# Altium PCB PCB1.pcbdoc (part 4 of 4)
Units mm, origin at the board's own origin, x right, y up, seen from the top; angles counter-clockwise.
Board outline 96.27 x 122.17 mm, 4 copper layers (Top Layer, Inner1, Inner2, Bottom Layer); 129 components, 127 nets, 708 pads, 342 vias.
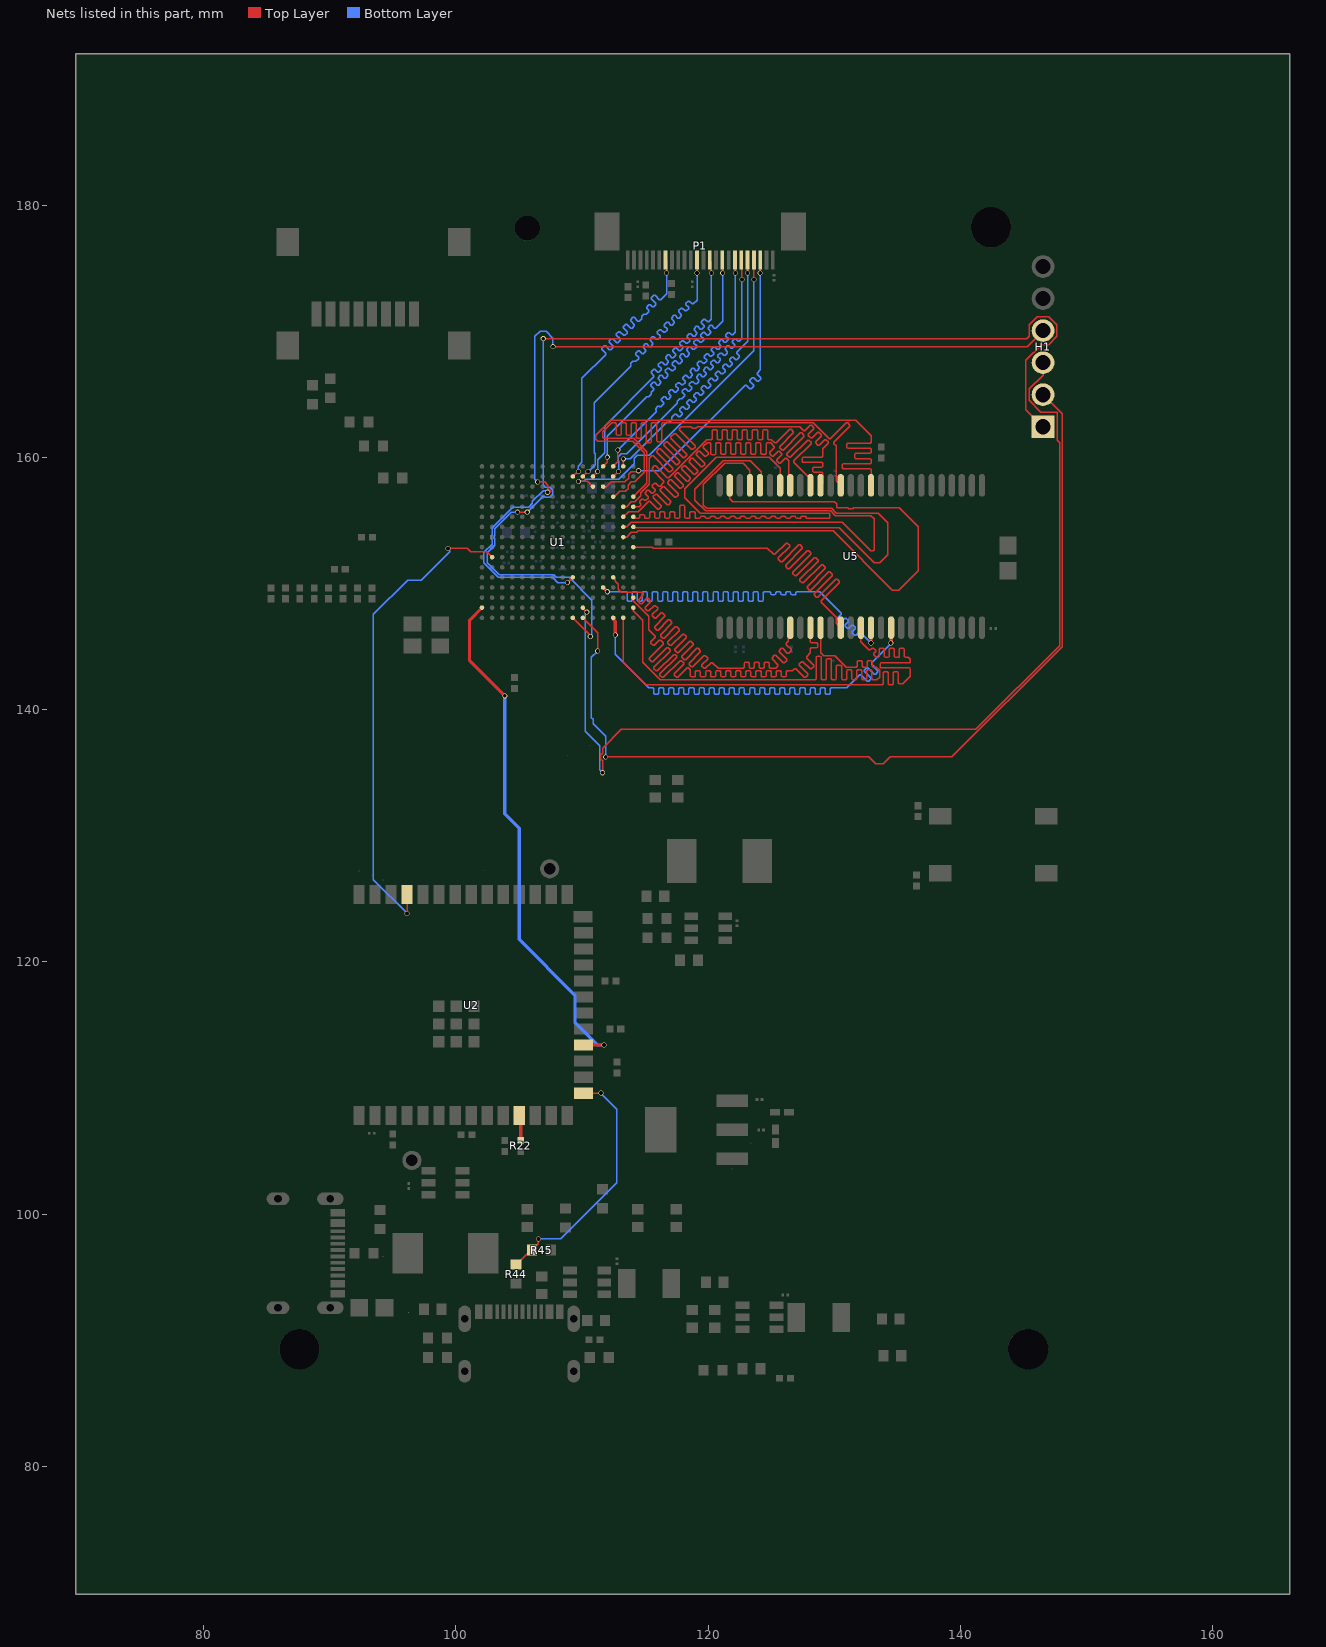
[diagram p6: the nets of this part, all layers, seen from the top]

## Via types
v1: diameter 0.4, hole 0.3, Top Layer to Bottom Layer, 308 vias
v2: diameter 1, hole 0.5, Top Layer to Bottom Layer, 33 vias
v3: diameter 0.5, hole 0.3, Top Layer to Bottom Layer, 1 vias

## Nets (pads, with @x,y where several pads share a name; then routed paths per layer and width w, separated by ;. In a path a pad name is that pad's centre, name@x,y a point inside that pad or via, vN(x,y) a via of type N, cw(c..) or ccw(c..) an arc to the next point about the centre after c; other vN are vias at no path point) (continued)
SD_DQ4: U1.M14 U5.8 | length 46.8
  Top Layer w0.1: U1.M14@112.477,150.489 112.659,150.307 112.659,150.175 112.895,149.939 112.895,149.531 113.119,149.307 114.766,149.307 114.87,149.203 114.87,149.103 114.449,148.682 114.449,148.582 114.632,148.399 114.732,148.399 115.153,148.82 115.253,148.82 115.436,148.637 115.436,148.537 115.015,148.116 115.015,148.016 115.197,147.833 115.297,147.833 115.719,148.254 115.819,148.254 116.002,148.072 116.002,147.972 115.58,147.55 115.58,147.45 115.763,147.267 115.863,147.267 116.284,147.689 116.384,147.689 116.578,147.496 116.578,147.396 115.768,146.587 115.768,146.487 115.951,146.304 116.051,146.304 116.86,147.113 116.96,147.113 117.133,146.94 117.133,146.84 116.232,145.939 116.232,145.839 116.415,145.656 116.515,145.656 117.416,146.557 117.516,146.557 117.699,146.375 117.699,146.275 116.798,145.374 116.798,145.274 116.981,145.091 117.081,145.091 117.982,145.992 118.082,145.992 118.264,145.809 118.264,145.709 117.363,144.808 117.363,144.708 117.546,144.525 117.646,144.525 118.547,145.426 118.647,145.426 118.83,145.243 118.83,145.143 117.929,144.242 117.929,144.142 118.112,143.959 118.212,143.959 119.113,144.86 119.213,144.86 119.396,144.678 119.396,144.578 118.495,143.677 118.495,143.577 118.678,143.394 118.778,143.394 119.679,144.295 119.779,144.295 119.961,144.112 119.961,144.012 119.507,143.558 119.507,143.458 119.69,143.275 119.79,143.275 120.244,143.729 120.344,143.729 120.798,143.275 122.781,143.275 122.852,143.346 122.852,143.693 122.923,143.764 123.181,143.764 123.252,143.693 123.252,143.346 123.323,143.275 123.581,143.275 123.652,143.346 123.652,143.693 123.723,143.764 123.981,143.764 124.052,143.693 124.052,143.346 124.123,143.275 124.381,143.275 124.452,143.346 124.452,143.693 124.523,143.764 124.781,143.764 124.852,143.693 124.852,143.346 124.923,143.275 125.35,143.275 125.533,143.458 125.533,143.558 125.07,144.02 125.07,144.12 125.253,144.303 125.353,144.303 125.954,143.703 126.054,143.703 126.236,143.886 126.236,143.986 125.636,144.586 125.636,144.686 125.819,144.869 125.919,144.869 126.294,144.493 126.394,144.493 126.577,144.676 126.577,144.776 126.202,145.152 126.202,145.252 126.365,145.415 126.365,146.351 U5.8@126.518,146.504
SD_DQ5: U1.P16 U5.10 | length 46.8
  Top Layer w0.1: U1.P16@114.077,148.889 114.077,148.629 115.316,147.39 115.316,146.331 115.815,145.832 115.815,145.732 115.464,145.381 115.464,145.281 115.647,145.098 115.747,145.098 116.148,145.499 116.248,145.499 116.457,145.29 116.457,145.19 115.351,144.083 115.351,143.983 115.534,143.8 115.634,143.8 116.74,144.907 116.84,144.907 116.997,144.75 116.997,144.65 115.704,143.358 115.704,143.258 115.887,143.075 115.987,143.075 117.279,144.368 117.406,144.368 117.499,144.275 117.499,144.175 116.174,142.85 116.174,142.75 116.357,142.567 116.457,142.567 117.782,143.892 117.882,143.892 118.058,143.716 118.058,143.589 117.319,142.85 117.319,142.75 117.502,142.567 117.602,142.567 118.341,143.306 118.441,143.306 118.598,143.149 118.598,142.667 118.669,142.596 118.927,142.596 118.998,142.667 118.998,143.004 119.069,143.075 119.327,143.075 119.398,143.004 119.398,142.667 119.469,142.596 119.727,142.596 119.798,142.667 119.798,143.004 119.869,143.075 120.127,143.075 120.198,143.004 120.198,142.667 120.269,142.596 120.527,142.596 120.598,142.667 120.598,143.004 120.669,143.075 120.927,143.075 120.998,143.004 120.998,142.667 121.069,142.596 121.327,142.596 121.398,142.667 121.398,143.004 121.469,143.075 121.727,143.075 121.798,143.004 121.798,142.667 121.869,142.596 122.127,142.596 122.198,142.667 122.198,143.004 122.269,143.075 122.527,143.075 122.598,143.004 122.598,142.667 122.669,142.596 122.927,142.596 122.998,142.667 122.998,143.004 123.069,143.075 123.327,143.075 123.398,143.004 123.398,142.667 123.469,142.596 123.727,142.596 123.798,142.667 123.798,143.004 123.869,143.075 124.127,143.075 124.198,143.004 124.198,142.667 124.269,142.596 124.527,142.596 124.598,142.667 124.598,143.004 124.669,143.075 124.927,143.075 124.998,143.004 124.998,142.667 125.069,142.596 125.327,142.596 125.398,142.667 125.398,143.004 125.469,143.075 125.727,143.075 125.798,143.004 125.798,142.667 125.869,142.596 126.127,142.596 126.198,142.667 126.198,143.004 126.269,143.075 126.692,143.075 126.859,143.242 126.959,143.242 127.634,142.567 127.734,142.567 127.917,142.75 127.917,142.85 127.242,143.525 127.242,143.625 127.425,143.808 127.525,143.808 128.099,143.234 128.199,143.234 128.381,143.417 128.381,143.517 127.808,144.091 127.808,144.191 128.118,144.501 128.118,144.823 128.189,144.893 128.618,144.893 128.689,144.964 128.689,145.223 128.618,145.293 128.189,145.293 128.118,145.364 U5.10@128.118,146.504
SD_DQ6: U1.R16 U5.11 | length 46.8
  Top Layer w0.1: U1.R16@114.077,148.089 114.077,147.858 114.829,147.106 114.829,143.743 116.205,142.367 128.511,142.367 128.581,142.438 128.581,144.179 128.652,144.249 128.911,144.249 128.981,144.179 128.981,142.438 129.052,142.367 129.311,142.367 129.381,142.438 129.381,143.984 129.452,144.055 129.711,144.055 129.781,143.984 129.781,142.438 129.852,142.367 130.111,142.367 130.181,142.438 130.181,143.456 130.252,143.526 130.511,143.526 130.581,143.456 130.581,142.438 130.652,142.367 130.911,142.367 130.981,142.438 130.981,143.083 131.052,143.154 131.311,143.154 131.381,143.083 131.381,142.438 131.452,142.367 131.711,142.367 131.781,142.438 131.781,143.083 131.852,143.154 132.111,143.154 132.181,143.083 132.181,142.438 132.252,142.367 132.511,142.367 132.581,142.438 132.581,143.083 132.652,143.154 132.911,143.154 132.981,143.083 132.981,142.438 133.052,142.367 133.389,142.367 133.604,142.582 133.604,143.129 133.35,143.383 133.107,143.383 133.037,143.454 133.037,143.82 132.966,143.891 132.707,143.891 132.637,143.82 132.637,143.454 132.566,143.383 132.307,143.383 132.237,143.454 132.237,143.82 132.166,143.891 131.907,143.891 131.837,143.82 131.837,143.454 131.766,143.383 130.937,143.383 130.036,144.284 129.159,144.284 128.918,144.525 U5.11@128.918,146.504
SD_DQ7: U1.J16 U5.13 | length 46.8
  Top Layer w0.1: U1.J16@114.077,152.889 115.588,152.889 115.66,152.817 124.694,152.817 125.201,152.31 125.301,152.31 126.193,153.202 126.293,153.202 126.476,153.019 126.476,152.919 125.584,152.027 125.584,151.927 125.767,151.745 125.867,151.745 127.194,153.072 127.294,153.072 127.477,152.889 127.477,152.789 126.149,151.462 126.149,151.362 126.332,151.179 126.432,151.179 127.869,152.616 127.969,152.616 128.152,152.433 128.152,152.333 126.715,150.896 126.715,150.796 126.898,150.613 126.998,150.613 128.435,152.05 128.535,152.05 128.718,151.867 128.718,151.767 127.281,150.33 127.281,150.23 127.464,150.048 127.564,150.048 129.001,151.485 129.101,151.485 129.284,151.302 129.284,151.202 127.847,149.765 127.847,149.665 128.029,149.482 128.129,149.482 129.566,150.919 129.666,150.919 129.849,150.736 129.849,150.636 128.412,149.199 128.412,149.099 128.595,148.916 128.695,148.916 130.132,150.353 130.232,150.353 130.415,150.17 130.415,150.07 128.978,148.633 128.978,148.533 130.17,147.341 130.17,146.852 U5.13@130.518,146.504
SD_DQ8: U1.D16 U5.42 | length 46.7
  Top Layer w0.1: U1.D16@114.077,156.889 115.156,157.968 115.156,160.463 114.103,161.516 111.733,161.516 111.633,161.616 111.633,162.023 112.351,162.741 112.644,162.741 112.714,162.67 112.714,161.816 112.785,161.745 113.044,161.745 113.114,161.816 113.114,162.67 113.185,162.741 113.444,162.741 113.514,162.67 113.514,161.816 113.585,161.745 113.844,161.745 113.914,161.816 113.914,162.67 113.985,162.741 114.244,162.741 114.314,162.67 114.314,161.587 114.385,161.517 114.644,161.517 114.714,161.587 114.714,162.67 114.785,162.741 115.044,162.741 115.114,162.67 115.114,161.234 115.185,161.163 115.444,161.163 115.514,161.234 115.514,162.67 115.585,162.741 115.844,162.741 115.914,162.67 115.914,161.304 115.985,161.234 116.244,161.234 116.314,161.304 116.314,162.67 116.385,162.741 128.343,162.741 129.602,161.482 129.702,161.482 130.96,162.741 131.06,162.741 131.243,162.558 131.243,162.458 129.985,161.199 129.985,161.099 130.17,160.914 130.17,158.136 U5.42@130.518,157.788
SD_DQ9: U1.E15 U5.44 | length 46.9
  Top Layer w0.1: U1.E15@113.277,156.089 113.537,156.089 113.919,156.471 114.199,156.471 114.681,156.953 114.681,157.21 115.356,157.885 115.356,159.933 115.538,160.115 115.638,160.115 116.9,158.853 117,158.853 117.183,159.036 117.183,159.136 115.921,160.398 115.921,160.498 116.104,160.681 116.204,160.681 117.466,159.419 117.566,159.419 117.749,159.602 117.749,159.702 116.487,160.964 116.487,161.064 116.67,161.247 116.77,161.247 118.032,159.985 118.132,159.985 118.314,160.168 118.314,160.268 117.053,161.53 117.053,161.63 117.321,161.898 117.421,161.898 118.682,160.636 118.782,160.636 118.965,160.819 118.965,160.919 117.703,162.18 117.703,162.28 117.856,162.433 118.643,162.433 118.77,162.306 119.043,162.306 119.17,162.433 127.254,162.433 127.578,162.109 127.678,162.109 128.111,162.541 128.211,162.541 128.394,162.358 128.394,162.258 127.961,161.826 127.961,161.726 128.144,161.543 128.244,161.543 128.68,161.979 128.78,161.979 128.963,161.796 128.963,161.696 128.527,161.26 128.527,161.16 128.71,160.977 128.81,160.977 129.246,161.414 129.346,161.414 129.529,161.231 129.529,161.131 129.093,160.694 129.093,160.594 129.098,160.589 129.098,160.077 129.027,160.006 127.522,160.006 127.452,159.935 127.452,159.677 127.522,159.606 129.027,159.606 129.098,159.535 129.098,159.277 129.027,159.206 128.389,159.206 128.319,159.135 128.319,158.877 128.389,158.806 129.027,158.806 129.098,158.735 129.098,157.968 U5.44@128.918,157.788
SD_DQ10: U1.E16 U5.45 | length 42.4
  Top Layer w0.1: U1.E16@114.077,156.089 114.56,156.089 114.681,156.21 114.681,156.31 114.572,156.419 114.572,156.519 114.755,156.702 114.855,156.702 114.964,156.593 115.064,156.593 115.247,156.776 115.247,156.876 115.009,157.114 115.009,157.214 115.192,157.396 115.292,157.396 115.529,157.158 115.629,157.158 115.812,157.341 115.812,157.441 115.574,157.679 115.574,157.779 115.757,157.962 115.857,157.962 116.095,157.724 116.195,157.724 116.493,158.022 116.493,158.122 115.556,159.06 115.556,159.16 115.739,159.343 115.839,159.343 116.776,158.405 116.876,158.405 119.888,161.417 120.251,161.417 120.322,161.488 120.322,162.133 120.393,162.204 120.651,162.204 120.722,162.133 120.722,161.488 120.793,161.417 121.051,161.417 121.122,161.488 121.122,162.133 121.193,162.204 121.451,162.204 121.522,162.133 121.522,161.488 121.593,161.417 121.851,161.417 121.922,161.488 121.922,162.133 121.993,162.204 122.251,162.204 122.322,162.133 122.322,161.488 122.393,161.417 122.651,161.417 122.722,161.488 122.722,162.133 122.793,162.204 123.051,162.204 123.122,162.133 123.122,161.488 123.193,161.417 123.451,161.417 123.522,161.488 123.522,162.133 123.593,162.204 123.851,162.204 123.922,162.133 123.922,161.488 123.993,161.417 124.251,161.417 124.322,161.488 124.322,162.133 124.393,162.204 124.651,162.204 124.722,162.133 124.722,161.488 124.793,161.417 125.029,161.417 125.298,161.147 125.398,161.147 126.484,162.233 126.584,162.233 126.767,162.05 126.767,161.95 125.681,160.864 125.681,160.764 125.864,160.581 125.964,160.581 127.323,161.94 127.423,161.94 127.606,161.757 127.606,161.657 126.247,160.299 126.247,160.199 126.43,160.016 126.53,160.016 127.888,161.374 127.988,161.374 128.171,161.191 128.171,161.091 126.813,159.733 126.813,159.633 128.118,158.327 U5.45@128.118,157.788
SD_DQ11: U1.F15 U5.47 | length 46.8
  Top Layer w0.1: U1.F15@113.277,155.289 113.695,155.707 114.461,155.707 115.279,156.526 115.379,156.526 116.008,155.897 116.108,155.897 116.291,156.08 116.291,156.18 115.662,156.808 115.662,156.908 115.845,157.091 115.945,157.091 116.778,156.258 116.878,156.258 117.061,156.441 117.061,156.541 116.228,157.374 116.228,157.474 116.411,157.657 116.511,157.657 117.344,156.824 117.444,156.824 117.627,157.007 117.627,157.107 116.794,157.94 116.794,158.04 116.977,158.223 117.077,158.223 117.752,157.547 117.852,157.547 118.035,157.73 118.035,157.83 117.359,158.506 117.359,158.606 117.542,158.788 117.642,158.788 118.318,158.112 118.418,158.112 118.601,158.295 118.601,158.395 117.925,159.071 117.925,159.171 118.108,159.354 118.208,159.354 118.884,158.678 118.984,158.678 119.167,158.861 119.167,158.961 118.491,159.637 118.491,159.737 118.674,159.92 118.774,159.92 119.45,159.244 119.55,159.244 119.732,159.427 119.732,159.527 119.056,160.203 119.056,160.303 119.239,160.485 119.339,160.485 119.735,160.089 119.835,160.089 120.018,160.272 120.018,160.372 119.622,160.768 119.622,160.868 119.917,161.163 120.147,161.163 120.218,161.092 120.218,160.27 120.289,160.199 120.547,160.199 120.618,160.27 120.618,161.092 120.689,161.163 120.927,161.163 120.997,161.092 120.997,160.32 121.068,160.249 121.327,160.249 121.397,160.32 121.397,161.092 121.468,161.163 121.727,161.163 121.797,161.092 121.797,160.32 121.868,160.249 122.127,160.249 122.197,160.32 122.197,161.092 122.268,161.163 122.527,161.163 122.597,161.092 122.597,160.32 122.668,160.249 122.927,160.249 122.997,160.32 122.997,161.092 123.068,161.163 123.327,161.163 123.397,161.092 123.397,160.32 123.468,160.249 123.727,160.249 123.797,160.32 123.797,161.092 123.868,161.163 124.127,161.163 124.197,161.092 124.197,160.32 124.268,160.249 124.527,160.249 124.597,160.32 124.597,161.092 124.668,161.163 124.968,161.163 125.265,160.866 125.265,160.766 124.893,160.393 124.893,160.293 125.075,160.11 125.175,160.11 125.548,160.483 125.648,160.483 125.831,160.3 125.831,160.2 125.458,159.827 125.458,159.727 125.641,159.544 125.741,159.544 126.114,159.917 126.214,159.917 126.391,159.74 126.391,157.915 U5.47@126.518,157.788
SD_DQ12: U1.F16 U5.48 | length 46.8
  Top Layer w0.1: U1.F16@114.077,155.289 114.2,155.166 114.496,155.166 114.567,155.237 114.567,155.402 114.637,155.473 114.896,155.473 114.967,155.402 114.967,155.237 115.037,155.166 115.296,155.166 115.367,155.237 115.367,155.631 115.437,155.702 115.696,155.702 115.767,155.631 115.767,155.237 115.837,155.166 116.096,155.166 116.167,155.237 116.167,155.631 116.237,155.702 116.496,155.702 116.567,155.631 116.567,155.237 116.637,155.166 116.896,155.166 116.967,155.237 116.967,155.631 117.037,155.702 117.296,155.702 117.367,155.631 117.367,155.237 117.437,155.166 117.696,155.166 117.767,155.237 117.767,156.139 117.837,156.21 118.096,156.21 118.167,156.139 118.167,155.237 118.237,155.166 118.496,155.166 118.567,155.237 118.567,155.631 118.637,155.702 118.896,155.702 118.967,155.631 118.967,155.237 119.037,155.166 119.296,155.166 119.367,155.237 119.367,155.256 119.437,155.327 119.696,155.327 119.767,155.256 119.767,155.237 119.837,155.166 120.096,155.166 120.167,155.237 120.167,155.256 120.237,155.327 120.496,155.327 120.567,155.256 120.567,155.237 120.637,155.166 120.896,155.166 120.967,155.237 120.967,155.256 121.037,155.327 121.296,155.327 121.367,155.256 121.367,155.237 121.437,155.166 121.696,155.166 121.767,155.237 121.767,155.256 121.837,155.327 122.096,155.327 122.167,155.256 122.167,155.237 122.237,155.166 122.496,155.166 122.567,155.237 122.567,155.256 122.637,155.327 122.896,155.327 122.967,155.256 122.967,155.237 123.037,155.166 123.296,155.166 123.367,155.237 123.367,155.256 123.437,155.327 123.696,155.327 123.767,155.256 123.767,155.237 123.837,155.166 124.096,155.166 124.167,155.237 124.167,155.256 124.237,155.327 124.496,155.327 124.567,155.256 124.567,155.237 124.637,155.166 124.896,155.166 124.967,155.237 124.967,155.256 125.037,155.327 125.296,155.327 125.367,155.256 125.367,155.237 125.437,155.166 125.696,155.166 125.767,155.237 125.767,155.256 125.837,155.327 126.096,155.327 126.167,155.256 126.167,155.237 126.237,155.166 126.496,155.166 126.567,155.237 126.567,155.256 126.637,155.327 126.896,155.327 126.967,155.256 126.967,155.237 127.037,155.166 127.296,155.166 127.367,155.237 127.367,155.256 127.437,155.327 127.696,155.327 127.767,155.256 127.767,155.237 127.837,155.166 129.639,155.166 129.667,155.194 129.667,155.517 129.628,155.556 119.399,155.556 118.154,156.801 118.154,157.524 120.65,160.02 124.841,160.02 125.718,159.143 U5.48@125.718,157.788
SD_DQ13: U1.G15 U5.50 | length 46.8
  Top Layer w0.1: U1.G15@113.277,154.489 113.537,154.489 113.919,154.871 130.625,154.871 132.896,152.6 133.096,152.6 133.169,152.673 133.169,155.121 132.915,155.375 130.092,155.375 129.711,155.756 119.805,155.756 118.962,156.6 118.962,157.471 121.223,159.733 123.35,159.733 124.206,158.877 124.206,157.876 U5.50@124.118,157.788
SD_DQ14: U1.G16 U5.51 | length 46.8
  Top Layer w0.1: U1.G16@114.077,154.489 114.134,154.432 130.39,154.432 133.184,151.638 133.604,151.638 134.239,152.273 134.239,154.813 133.477,155.575 130.175,155.575 129.794,155.956 119.888,155.956 119.634,156.21 119.634,157.861 121.306,159.533 122.788,159.533 123.318,159.003 U5.51@123.318,157.788
SD_DQ15: U1.H15 U5.53 | length 46.8
  Top Layer w0.1: U1.H15@113.277,153.689 113.537,153.689 113.919,154.071 114.366,154.071 114.466,154.171 129.914,154.171 134.606,149.479 135.109,149.479 136.652,151.022 136.652,154.507 135.155,156.004 131.553,156.004 131.485,155.935 131.151,155.935 131.083,156.004 130.203,156.004 130.203,156.309 130.02,156.492 128.357,156.492 121.939,156.492 121.718,156.713 U5.53@121.718,157.788
SD_DQM0: U1.T15 U5.15 | length 46.8
  Top Layer w0.1: U1.T15@113.277,147.289 113.277,143.771 115.062,141.986 133.822,141.986 133.892,142.057 133.892,142.931 133.963,143.002 134.222,143.002 134.292,142.931 134.292,142.057 134.363,141.986 134.622,141.986 134.692,142.057 134.692,142.931 134.763,143.002 135.022,143.002 135.092,142.931 135.092,142.127 135.163,142.057 135.453,142.057 136.044,142.648 136.044,143.235 135.973,143.306 133.71,143.306 133.639,143.377 133.639,143.635 133.71,143.706 135.973,143.706 136.044,143.777 136.044,143.991 135.89,144.145 135.641,144.145 135.571,144.216 135.571,144.786 135.5,144.857 135.241,144.857 135.171,144.786 135.171,144.216 135.1,144.145 134.841,144.145 134.771,144.216 134.771,144.786 134.7,144.857 134.441,144.857 134.371,144.786 134.371,144.216 134.3,144.145 134.041,144.145 133.971,144.216 133.971,144.786 133.9,144.857 133.641,144.857 133.571,144.786 133.571,144.216 133.5,144.145 133.35,144.145 133.138,144.357 133.138,144.457 133.284,144.603 133.284,144.703 133.101,144.886 133.001,144.886 132.855,144.74 132.755,144.74 132.118,145.377 U5.15@132.118,146.504
SD_DQM1: U1.D14 U5.39 | length 46.8
  Top Layer w0.1: U1.D14@112.477,156.889 112.566,156.889 112.984,157.307 113.435,157.307 113.659,157.531 113.659,157.811 113.919,158.071 114.199,158.071 114.956,158.828 114.956,160.38 114.046,161.29 111.252,161.29 111.095,161.447 111.095,161.768 112.268,162.941 131.699,162.941 132.927,161.713 132.927,161.186 132.856,161.115 131.086,161.115 131.015,161.044 131.015,160.786 131.086,160.715 132.856,160.715 132.927,160.644 132.927,160.386 132.856,160.315 131.685,160.315 131.614,160.244 131.614,159.986 131.685,159.915 132.856,159.915 132.927,159.844 132.927,159.586 132.856,159.515 130.721,159.515 130.651,159.444 130.651,159.186 130.721,159.115 132.856,159.115 132.927,159.044 132.927,158.042 U5.39@132.8,157.915
SD_RAS_N: U1.T14 U5.18 | length 46.9
  Top Layer w0.254: U1.T14@112.522,147.123 112.649,146.996 v1(112.649,145.923) ; v1(134.493,145.288) 134.518,145.313 U5.18@134.518,146.504
  Bottom Layer w0.1: v1(112.649,145.923) 112.649,144.399 115.316,141.732 115.616,141.732 115.687,141.661 115.687,141.295 115.757,141.224 116.016,141.224 116.087,141.295 116.087,141.661 116.157,141.732 116.416,141.732 116.487,141.661 116.487,141.295 116.557,141.224 116.816,141.224 116.887,141.295 116.887,141.661 116.957,141.732 117.216,141.732 117.287,141.661 117.287,141.295 117.357,141.224 117.616,141.224 117.687,141.295 117.687,141.661 117.757,141.732 118.016,141.732 118.087,141.661 118.087,141.295 118.157,141.224 118.416,141.224 118.487,141.295 118.487,141.661 118.557,141.732 118.816,141.732 118.887,141.661 118.887,141.295 118.957,141.224 119.216,141.224 119.287,141.295 119.287,141.661 119.357,141.732 119.616,141.732 119.687,141.661 119.687,141.295 119.757,141.224 120.016,141.224 120.087,141.295 120.087,141.661 120.157,141.732 120.416,141.732 120.487,141.661 120.487,141.295 120.557,141.224 120.816,141.224 120.887,141.295 120.887,141.661 120.957,141.732 121.216,141.732 121.287,141.661 121.287,141.295 121.357,141.224 121.616,141.224 121.687,141.295 121.687,141.661 121.757,141.732 122.016,141.732 122.087,141.661 122.087,141.295 122.157,141.224 122.416,141.224 122.487,141.295 122.487,141.661 122.557,141.732 122.816,141.732 122.887,141.661 122.887,141.295 122.957,141.224 123.216,141.224 123.287,141.295 123.287,141.661 123.357,141.732 123.616,141.732 123.687,141.661 123.687,141.295 123.757,141.224 124.016,141.224 124.087,141.295 124.087,141.661 124.157,141.732 124.416,141.732 124.487,141.661 124.487,141.295 124.557,141.224 124.816,141.224 124.887,141.295 124.887,141.661 124.957,141.732 125.216,141.732 125.287,141.661 125.287,141.295 125.357,141.224 125.616,141.224 125.687,141.295 125.687,141.661 125.757,141.732 126.016,141.732 126.087,141.661 126.087,141.295 126.157,141.224 126.416,141.224 126.487,141.295 126.487,141.661 126.557,141.732 126.816,141.732 126.887,141.661 126.887,141.295 126.957,141.224 127.216,141.224 127.287,141.295 127.287,141.661 127.357,141.732 127.616,141.732 127.687,141.661 127.687,141.295 127.757,141.224 128.016,141.224 128.087,141.295 128.087,141.661 128.157,141.732 128.416,141.732 128.487,141.661 128.487,141.295 128.557,141.224 128.816,141.224 128.887,141.295 128.887,141.661 128.957,141.732 129.216,141.732 129.287,141.661 129.287,141.295 129.357,141.224 129.616,141.224 129.687,141.295 129.687,141.661 129.757,141.732 130.985,141.732 132.014,142.761 132.114,142.761 132.625,142.25 132.725,142.25 132.908,142.433 132.908,142.533 132.397,143.044 132.397,143.144 132.579,143.327 132.679,143.327 133.191,142.816 133.291,142.816 133.473,142.998 133.473,143.098 132.962,143.61 132.962,143.71 134.493,145.24 v1(134.493,145.288)
SD_WE_N: U1.N13 U5.16 | length 46.8
  Top Layer w0.254: U1.N13@111.677,149.689 v1(112.014,149.352) ; v1(132.918,145.288) U5.16@132.918,146.504
  Bottom Layer w0.1: v1(112.014,149.352) 113.522,149.352 113.593,149.281 113.593,148.661 113.664,148.59 113.922,148.59 113.993,148.661 113.993,149.281 114.064,149.352 114.322,149.352 114.393,149.281 114.393,148.661 114.464,148.59 114.722,148.59 114.793,148.661 114.793,149.281 114.864,149.352 115.122,149.352 115.193,149.281 115.193,148.661 115.264,148.59 115.522,148.59 115.593,148.661 115.593,149.281 115.664,149.352 115.922,149.352 115.993,149.281 115.993,148.661 116.064,148.59 116.322,148.59 116.393,148.661 116.393,149.281 116.464,149.352 116.722,149.352 116.793,149.281 116.793,148.661 116.864,148.59 117.122,148.59 117.193,148.661 117.193,149.281 117.264,149.352 117.522,149.352 117.593,149.281 117.593,148.661 117.664,148.59 117.922,148.59 117.993,148.661 117.993,149.281 118.064,149.352 118.322,149.352 118.393,149.281 118.393,148.661 118.464,148.59 118.722,148.59 118.793,148.661 118.793,149.281 118.864,149.352 119.122,149.352 119.193,149.281 119.193,148.661 119.264,148.59 119.522,148.59 119.593,148.661 119.593,149.281 119.664,149.352 119.922,149.352 119.993,149.281 119.993,148.661 120.064,148.59 120.322,148.59 120.393,148.661 120.393,149.281 120.464,149.352 120.722,149.352 120.793,149.281 120.793,148.661 120.864,148.59 121.122,148.59 121.193,148.661 121.193,149.281 121.264,149.352 121.522,149.352 121.593,149.281 121.593,148.661 121.664,148.59 121.922,148.59 121.993,148.661 121.993,149.281 122.064,149.352 122.322,149.352 122.393,149.281 122.393,148.661 122.464,148.59 122.722,148.59 122.793,148.661 122.793,149.281 122.864,149.352 123.122,149.352 123.193,149.281 123.193,148.661 123.264,148.59 123.522,148.59 123.593,148.661 123.593,149.281 123.664,149.352 123.922,149.352 123.993,149.281 123.993,148.661 124.064,148.59 124.322,148.59 124.393,148.661 124.393,149.281 124.464,149.352 124.901,149.352 124.972,149.281 124.972,149.169 125.043,149.098 125.301,149.098 125.372,149.169 125.372,149.281 125.443,149.352 125.701,149.352 125.772,149.281 125.772,149.169 125.843,149.098 126.101,149.098 126.172,149.169 126.172,149.281 126.243,149.352 126.501,149.352 126.572,149.281 126.572,149.169 126.643,149.098 126.901,149.098 126.972,149.169 126.972,149.281 127.043,149.352 128.854,149.352 130.554,147.652 130.554,147.552 130.298,147.297 130.298,147.197 130.481,147.014 130.581,147.014 130.837,147.269 130.937,147.269 131.119,147.086 131.119,146.986 130.864,146.731 130.864,146.631 131.047,146.448 131.147,146.448 131.402,146.704 131.502,146.704 131.685,146.521 131.685,146.421 131.43,146.165 131.43,146.065 131.613,145.882 131.713,145.882 131.968,146.138 132.068,146.138 v1(132.918,145.288)
SDA: R22.1 U2.11 | length 1.9
  Top Layer w0.254: R22.1@105.151,105.918 U2.11@105.151,107.836
SSPI_CS_N: U1.R1 U2.18 | length 41.3
  Top Layer w0.254: U1.R1@102.077,148.089 101.092,147.104 101.092,143.891 v1(103.886,141.097) ; U2.18@110.241,113.411 v1(111.76,113.411)
  Bottom Layer w0.254: v1(103.886,141.097) 103.886,131.743 105.029,130.6 105.029,121.793 109.447,117.375 109.447,115.216 111.252,113.411 v1(111.76,113.411)
TCK: H1.1 U1.T10 | length 88.4
  Top Layer w0.1: v1(104.898,155.661) 105.109,155.661 105.119,155.671 105.435,155.671 105.445,155.661 105.623,155.661 v1@105.664,155.702 ; v1(106.934,169.418) 145.272,169.418 145.456,169.602 145.456,170.509 146.102,171.155 147.014,171.155 147.66,170.509 147.66,169.597 147.014,168.951 146.438,168.951 145.205,167.719 145.205,163.786 H1.1@146.558,162.433 ; U1.T10@109.277,147.289 110.661,145.905 v1(110.661,145.796)
  Bottom Layer w0.1: v1(104.898,155.661) 104.382,155.661 103.079,154.358 103.079,153.802 103.03,153.752 103.03,153.6 103.091,153.538 103.091,153.04 102.489,152.438 102.489,151.667 103.461,150.695 107.76,150.695 107.973,150.481 109.006,150.481 110.792,148.695 110.792,145.927 v1(110.661,145.796) ; v1(105.664,155.661) 106.934,156.931 107.019,156.931 107.111,156.839 107.444,156.839 107.679,157.075 107.679,157.408 107.444,157.643 107.111,157.643 106.934,157.82 v1(106.934,169.418)
TDI: H1.3 U1.R11 | length 80.2
  Top Layer w0.1: U1.R11@110.077,148.089 110.077,148.041 v1(110.39,147.728) ; v1(111.633,135.001) 111.633,135.935 111.485,136.083 111.485,136.417 111.633,136.565 111.633,136.946 113.117,138.43 141.224,138.43 147.882,145.088 147.882,161.153 147.669,161.366 147.669,163.579 146.393,163.579 145.456,164.517 145.456,165.429 146.558,166.531 H1.3@146.558,167.513
  Bottom Layer w0.1: v1(110.39,147.728) 110.259,147.597 110.259,138.291 111.402,137.148 111.402,135.232 v1(111.633,135.001)
TDO: H1.4 U1.M10 | length 72.1
  Top Layer w0.1: v1(106.489,158.054) 106.701,158.054 106.719,158.071 107.035,158.071 107.295,157.811 107.295,157.531 107.519,157.307 107.519,157.271 107.489,157.241 v1(107.277,157.241) ; v1(107.696,168.783) 145.288,168.783 H1.4@146.558,170.053 ; v1(108.839,150.079) 108.867,150.079 U1.M10@109.277,150.489
  Bottom Layer w0.1: v1(106.489,158.054) 106.278,158.265 106.278,169.601 106.678,170.001 107.159,170.001 107.696,169.464 v1(107.696,168.783) ; v1(107.277,157.241) 107.15,157.368 106.921,157.368 106.066,156.514 106.066,156.357 105.772,156.063 104.501,156.063 102.879,154.441 102.879,153.884 102.83,153.835 102.83,153.517 102.891,153.456 102.891,153.122 102.235,152.466 102.235,151.638 103.378,150.495 107.677,150.495 108.092,150.079 v1(108.839,150.079)
TMS: H1.2 U1.T11 | length 73.1
  Top Layer w0.1: U1.T11@110.077,147.289 111.252,146.114 v1(111.252,144.653) ; v1(111.887,136.25) 132.759,136.25 133.313,135.696 133.895,135.696 134.449,136.25 139.327,136.25 148.082,145.005 148.082,163.449 H1.2@146.558,164.973
  Bottom Layer w0.1: v1(111.252,144.653) 110.744,144.145 110.744,139.38 110.892,139.232 110.892,138.898 111.887,137.903 v1(111.887,136.25)
TX: U1.K2 U2.37 | length 38.6
  Top Layer w0.1: v1@96.134,123.825 U2.37@96.134,125.336 ; v1@99.314,152.781 100.904,152.781 101.179,152.506 102.458,152.506 ; 102.459,152.507 U1.K2@102.877,152.089
  Bottom Layer w0.1: v1(96.134,123.846) 93.472,126.508 93.472,147.57 96.176,150.274 97.15,150.274 97.157,150.281 97.27,150.281 99.509,152.52 99.509,152.661 v1(99.389,152.781)
USB_VBUS: R44.1 R45.2 U2.15 | length 19.9
  Top Layer w0.1: R44.1@104.775,96.003 105.927,97.155 R45.2@106.054,97.155 106.553,97.654 v1(106.553,98.044) ; U2.15@110.114,109.601 v1(111.506,109.601)
  Bottom Layer w0.1: v1(106.553,98.044) 108.331,98.044 112.776,102.489 112.776,108.331 v1(111.506,109.601)
VSYNC: P1.7 U1.B10 | length 27.1
  Top Layer w0.1: U1.B10@109.277,158.489 109.673,158.885 v1(109.72,158.885) ; P1.7@116.634,175.655 116.713,175.577 v1(116.713,174.625)
  Bottom Layer w0.1: v1(109.72,158.885) 109.72,159.317 110.003,159.599 110.003,166.264 111.898,168.159 111.898,168.259 111.589,168.568 111.589,168.668 111.772,168.851 111.872,168.851 112.181,168.542 112.281,168.542 112.464,168.725 112.464,168.825 112.155,169.134 112.155,169.234 112.337,169.417 112.437,169.417 112.747,169.108 112.847,169.108 113.029,169.29 113.029,169.39 112.72,169.7 112.72,169.8 112.903,169.982 113.003,169.982 113.312,169.673 113.412,169.673 113.595,169.856 113.595,169.956 113.286,170.265 113.286,170.365 113.469,170.548 113.569,170.548 113.878,170.239 113.978,170.239 114.161,170.422 114.161,170.522 113.852,170.831 113.852,170.931 114.035,171.114 114.135,171.114 114.444,170.805 114.544,170.805 114.73,170.991 114.73,171.184 114.917,171.37 115.109,171.37 115.292,171.553 115.292,171.653 115.126,171.819 115.126,171.919 115.309,172.102 115.409,172.102 115.575,171.936 115.675,171.936 115.858,172.119 115.858,172.219 115.513,172.563 115.513,172.663 115.696,172.846 115.796,172.846 116.141,172.502 116.241,172.502 116.713,172.974 v1(116.713,174.625)
Y2: P1.19 U1.B14 | length 27
  Top Layer w0.1: U1.B14@112.477,158.489 112.865,158.877 v1(112.903,158.877) ; P1.19@122.634,175.655 122.682,175.607 v1(122.682,174.117)
  Bottom Layer w0.1: v1(112.903,158.877) 112.903,159.705 112.882,159.726 112.882,160.06 113.117,160.295 113.559,160.295 117.563,164.299 117.563,164.465 117.764,164.665 117.929,164.665 118.145,164.881 118.145,164.981 117.957,165.169 117.957,165.269 118.139,165.451 118.239,165.451 118.427,165.263 118.527,165.263 118.71,165.446 118.71,165.546 118.522,165.734 118.522,165.834 118.705,166.017 118.805,166.017 118.993,165.829 119.093,165.829 119.276,166.012 119.276,166.112 119.088,166.3 119.088,166.4 119.271,166.583 119.371,166.583 119.559,166.395 119.659,166.395 119.842,166.578 119.842,166.678 119.654,166.866 119.654,166.966 119.837,167.148 119.937,167.148 120.125,166.961 120.225,166.961 120.407,167.143 120.407,167.243 120.219,167.431 120.219,167.531 120.402,167.714 120.502,167.714 120.69,167.526 120.79,167.526 120.973,167.709 120.973,167.809 120.785,167.997 120.785,168.097 120.968,168.28 121.068,168.28 121.256,168.092 121.356,168.092 121.539,168.275 121.539,168.375 121.351,168.563 121.351,168.663 121.534,168.846 121.634,168.846 121.822,168.658 121.922,168.658 122.104,168.84 122.104,168.94 121.916,169.128 121.916,169.228 122.099,169.411 122.199,169.411 122.387,169.223 122.487,169.223 122.682,169.418 v1(122.682,174.117)
Y3: P1.21 U1.C12 | length 27
  Top Layer w0.1: v1(109.714,158.1) 110.466,158.1 U1.C12@110.877,157.689 ; v1(123.636,174.117) P1.21@123.636,175.652
  Bottom Layer w0.1: v1(109.714,158.1) 110.163,158.1 110.322,158.259 112.92,158.259 114.152,159.491 114.152,159.933 114.387,160.168 115.337,160.168 123.636,168.467 v1(123.636,174.117)
Y4: P1.22 U1.C13 | length 27
  Top Layer w0.1: U1.C13@111.677,157.689 111.937,157.689 112.319,158.071 113.399,158.071 113.695,158.367 113.695,158.647 113.919,158.871 114.411,158.871 v1(114.486,158.945) ; v1(124.136,174.625) P1.22@124.136,175.652
  Bottom Layer w0.1: v1(114.486,158.945) 116.146,158.945 122.941,165.74 123.041,165.74 123.322,165.459 123.422,165.459 123.605,165.642 123.605,165.742 123.324,166.023 123.324,166.123 123.507,166.306 123.607,166.306 123.888,166.025 123.988,166.025 124.171,166.208 124.171,166.308 123.89,166.589 123.89,166.689 124.136,166.935 v1(124.136,174.625)
Y5: P1.20 U1.A15 | length 27
  Top Layer w0.1: U1.A15@113.277,159.289 113.284,159.296 v1(113.284,159.893) ; v1(123.136,174.625) P1.20@123.136,175.652
  Bottom Layer w0.1: v1(113.284,159.893) 113.83,159.893 116.727,162.791 116.827,162.791 116.835,162.782 116.935,162.782 117.118,162.965 117.118,163.065 117.11,163.074 117.11,163.174 117.37,163.434 117.47,163.434 117.669,163.235 117.769,163.235 117.952,163.418 117.952,163.518 117.753,163.717 117.753,163.817 117.936,163.999 118.036,163.999 118.235,163.801 118.335,163.801 118.518,163.984 118.518,164.084 118.319,164.282 118.319,164.382 118.502,164.565 118.602,164.565 118.8,164.366 118.9,164.366 119.083,164.549 119.083,164.649 118.885,164.848 118.885,164.948 119.067,165.131 119.167,165.131 119.366,164.932 119.466,164.932 119.649,165.115 119.649,165.215 119.45,165.414 119.45,165.514 119.633,165.696 119.733,165.696 119.932,165.498 120.032,165.498 120.215,165.681 120.215,165.781 120.016,165.979 120.016,166.079 120.199,166.262 120.299,166.262 120.497,166.063 120.597,166.063 120.78,166.246 120.78,166.346 120.582,166.545 120.582,166.645 120.764,166.828 120.864,166.828 121.063,166.629 121.163,166.629 121.346,166.812 121.346,166.912 121.147,167.111 121.147,167.211 121.33,167.393 121.43,167.393 121.629,167.195 121.729,167.195 121.912,167.378 121.912,167.478 121.713,167.676 121.713,167.776 121.896,167.959 121.996,167.959 122.194,167.76 122.294,167.76 122.477,167.943 122.477,168.043 122.279,168.242 122.279,168.342 123.136,169.199 v1(123.136,174.625)
Y6: P1.18 U1.A14 | length 27.1
  Top Layer w0.1: U1.A14@112.477,159.289 112.842,159.654 v1(112.842,160.589) ; P1.18@122.134,175.655 122.174,175.615 v1(122.174,174.625)
  Bottom Layer w0.1: v1(112.842,160.589) 115.881,163.627 115.881,163.727 115.835,163.772 115.835,163.872 116.018,164.055 116.118,164.055 116.164,164.01 116.264,164.01 116.493,164.239 116.493,164.339 116.307,164.524 116.307,164.624 116.49,164.807 116.59,164.807 116.775,164.621 116.875,164.621 117.058,164.804 117.058,164.904 116.873,165.09 116.873,165.19 117.056,165.372 117.156,165.372 117.341,165.187 117.441,165.187 117.624,165.37 117.624,165.47 117.439,165.655 117.439,165.755 117.621,165.938 117.721,165.938 117.907,165.753 118.007,165.753 118.19,165.936 118.19,166.036 118.004,166.221 118.004,166.321 118.187,166.504 118.287,166.504 118.472,166.318 118.572,166.318 118.755,166.501 118.755,166.601 118.57,166.787 118.57,166.887 118.753,167.07 118.853,167.07 119.038,166.884 119.138,166.884 119.321,167.067 119.321,167.167 119.136,167.352 119.136,167.452 119.318,167.635 119.418,167.635 119.604,167.45 119.704,167.45 119.887,167.633 119.887,167.733 119.701,167.918 119.701,168.018 119.884,168.201 119.984,168.201 120.169,168.016 120.269,168.016 120.452,168.198 120.452,168.298 120.267,168.484 120.267,168.584 120.45,168.767 120.55,168.767 120.735,168.581 120.835,168.581 121.018,168.764 121.018,168.864 120.833,169.049 120.833,169.149 121.016,169.332 121.116,169.332 121.301,169.147 121.401,169.147 121.584,169.33 121.584,169.43 121.398,169.615 121.398,169.715 121.581,169.898 121.681,169.898 121.867,169.713 121.967,169.713 122.174,169.92 v1(122.174,174.625)
Y7: P1.16 U1.A13 | length 27
  Top Layer w0.1: U1.A13@111.677,159.289 112.014,159.626 v1(112.014,160.02) ; P1.16@121.134,175.654 121.158,175.63 v1(121.158,174.625)
  Bottom Layer w0.1: v1(112.014,160.02) 112.014,161.671 115.153,164.81 115.295,164.81 115.507,165.022 115.507,165.164 115.692,165.349 115.692,165.449 115.475,165.667 115.475,165.767 115.657,165.949 115.757,165.949 115.975,165.732 116.075,165.732 116.258,165.915 116.258,166.015 116.04,166.232 116.04,166.332 116.223,166.515 116.323,166.515 116.541,166.298 116.641,166.298 116.823,166.48 116.823,166.58 116.606,166.798 116.606,166.898 116.789,167.081 116.889,167.081 117.106,166.863 117.206,166.863 117.389,167.046 117.389,167.146 117.172,167.364 117.172,167.464 117.354,167.646 117.454,167.646 117.672,167.429 117.772,167.429 117.955,167.612 117.955,167.712 117.737,167.929 117.737,168.029 117.92,168.212 118.02,168.212 118.238,167.995 118.338,167.995 118.52,168.177 118.52,168.277 118.303,168.495 118.303,168.595 118.486,168.778 118.586,168.778 118.803,168.56 118.903,168.56 119.086,168.743 119.086,168.843 118.869,169.061 118.869,169.161 119.051,169.343 119.151,169.343 119.369,169.126 119.469,169.126 119.652,169.309 119.652,169.409 119.434,169.626 119.434,169.726 119.617,169.909 119.717,169.909 119.935,169.692 120.035,169.692 120.217,169.874 120.217,169.974 120,170.192 120,170.292 120.183,170.475 120.283,170.475 120.5,170.257 120.6,170.257 121.158,170.815 v1(121.158,174.625)
Y8: P1.14 U1.B12 | length 27
  Top Layer w0.1: U1.B12@110.877,158.489 111.252,158.864 v1(111.252,158.877) ; P1.14@120.135,175.655 120.265,175.524 v1(120.265,174.621)
  Bottom Layer w0.1: v1(111.252,158.877) 111.252,159.827 111.814,160.389 111.814,162.487 115.712,166.385 115.712,166.485 115.494,166.702 115.494,166.802 115.677,166.985 115.777,166.985 115.995,166.768 116.095,166.768 116.288,166.961 116.288,167.061 116.071,167.279 116.071,167.379 116.254,167.562 116.354,167.562 116.571,167.344 116.671,167.344 116.854,167.527 116.854,167.627 116.636,167.844 116.636,167.944 116.819,168.127 116.919,168.127 117.137,167.91 117.237,167.91 117.42,168.093 117.42,168.193 117.202,168.41 117.202,168.51 117.385,168.693 117.485,168.693 117.702,168.475 117.802,168.475 117.985,168.658 117.985,168.758 117.768,168.976 117.768,169.076 117.951,169.259 118.051,169.259 118.268,169.041 118.368,169.041 118.551,169.224 118.551,169.324 118.333,169.541 118.333,169.641 118.516,169.824 118.616,169.824 118.834,169.607 118.934,169.607 119.117,169.79 119.117,169.89 118.899,170.107 118.899,170.207 119.082,170.39 119.182,170.39 119.4,170.173 119.5,170.173 119.682,170.355 119.682,170.455 119.465,170.673 119.465,170.773 119.648,170.956 119.748,170.956 119.965,170.738 120.065,170.738 120.265,170.938 v1(120.265,174.621)
Y9: P1.12 U1.B11 | length 27
  Top Layer w0.1: U1.B11@110.077,158.489 110.465,158.877 v1(110.49,158.877) ; v1(119.135,174.625) P1.12@119.135,175.655
  Bottom Layer w0.1: v1(110.49,158.877) 111.052,159.439 111.052,160.286 110.977,160.361 110.977,164.317 113.889,167.229 113.889,167.329 113.862,167.356 113.862,167.456 114.045,167.639 114.145,167.639 114.172,167.612 114.272,167.612 114.498,167.838 114.498,167.938 114.281,168.156 114.281,168.256 114.464,168.439 114.564,168.439 114.781,168.221 114.881,168.221 115.064,168.404 115.064,168.504 114.846,168.721 114.846,168.821 115.029,169.004 115.129,169.004 115.347,168.787 115.447,168.787 115.63,168.97 115.63,169.07 115.412,169.287 115.412,169.387 115.595,169.57 115.695,169.57 115.913,169.353 116.013,169.353 116.195,169.535 116.195,169.635 115.978,169.853 115.978,169.953 116.161,170.136 116.261,170.136 116.478,169.918 116.578,169.918 116.761,170.101 116.761,170.201 116.544,170.419 116.544,170.519 116.726,170.701 116.826,170.701 117.044,170.484 117.144,170.484 117.327,170.667 117.327,170.767 117.109,170.984 117.109,171.084 117.292,171.267 117.392,171.267 117.61,171.05 117.71,171.05 117.892,171.232 117.892,171.332 117.675,171.55 117.675,171.65 117.858,171.833 117.958,171.833 118.175,171.615 118.275,171.615 118.458,171.798 118.458,171.898 118.241,172.116 118.241,172.216 118.423,172.398 118.523,172.398 118.741,172.181 118.841,172.181 119.135,172.475 v1(119.135,174.625)
pads on no net: P1.1 P1.10 SCREW1.1 SCREW2.1 SCREW3.1 SCREW4.1 U1.A9 U1.B3 U1.B8 U1.B13 U1.B15 U1.B16 U1.C1 U1.C2 U1.C3 U1.C4 U1.C5 U1.C6 U1.C9 U1.C10 U1.C11 U1.C14 U1.C15 U1.C16 U1.D1 U1.D3 U1.D4 U1.D5 U1.D6 U1.D7 U1.D8 U1.D9 U1.D10 U1.D11 U1.D12 U1.D13 U1.E3 U1.E4 U1.E5 U1.E6 U1.E7 U1.E8 U1.E9 U1.E10 U1.E11 U1.E12 U1.E13 U1.E14 U1.F3 U1.F4 U1.F5 U1.F12 U1.F13 U1.F14 U1.G3 U1.G4 U1.G5 U1.G12 U1.G13 U1.G14 U1.H2 U1.H3 U1.H4 U1.H5 U1.H12 U1.H13 U1.H14 U1.J3 U1.J4 U1.J5 U1.J12 U1.J13 U1.K3 U1.K4 U1.K5 U1.K13 U1.K14 U1.K15 U1.L1 U1.L2 U1.L3 U1.L4 U1.L5 U1.L13 U1.L14 U1.L16 U1.M2 U1.M3 U1.M4 U1.M5 U1.M6 U1.M7 U1.M9 U1.M11 U1.M12 U1.M13 U1.N1 U1.N3 U1.N4 U1.N5 U1.N6 U1.N7 U1.N8 U1.N9 U1.N11 U1.N12 U1.N14 U1.N16 U1.P1 U1.P2 U1.P3 U1.P4 U1.P5 U1.P6 U1.P7 U1.P8 U1.P11 U1.P12 U1.P13 U1.P14 U1.P15 U1.R2 U1.R3 U1.R4 U1.R5 U1.R6 U1.R7 U1.R8 U1.R12 U1.R14 U1.T13 U2.4 U2.16 U2.26 U2.28 U2.29 U2.30 U2.32 U2.33 U2.34 U2.35 U2.38 U2.39 U5.40 U8.4 USB1.A6 USB1.A7 USB1.A8 USB1.B6 USB1.B7 USB1.B8 USB2.A8 USB2.B6 USB2.B7 USB2.B8
copper on no net: | length 14.2
  Top Layer w0.1: 93.345,126.873 93.594,126.624 93.594,125.336 ; 94.234,126.492 94.864,125.862 94.864,125.336 ; 96.134,107.836 96.363,107.607 v1(96.363,106.202) ; 105.024,125.336 105.024,125.971 106.561,127.508 107.188,127.508 107.442,127.254 ; v1(109.729,148.589) 109.778,148.59 110.077,148.889
  Top Layer w0.254: v1(101.473,148.54) 101.728,148.54 102.077,148.889 ; v1(103.272,149.246) 103.272,149.284 103.677,149.689 ; v1(104.029,148.489) 104.077,148.489 104.477,148.889 ; v1(104.14,149.352) 104.477,149.689
  Bottom Layer w0.1: v1(96.363,106.202) 96.52,106.045 96.52,104.267 ; v1(109.729,148.589) 110.109,148.209 110.109,148.082

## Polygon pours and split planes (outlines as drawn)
+5V on Inner2 (solid, remove dead copper): 87.022,103.749 105.49,103.749 105.49,88.615 87.022,88.615
GND on Inner1 (solid, remove dead copper): 76.2,182.626 151.257,182.626 151.257,78.486 76.2,78.486
+5V on Top Layer (solid, remove dead copper, pour order 0): 86.741,99.695 89.878,99.695 89.878,93.641 86.741,93.641
+3V3 on Inner2 (solid, remove dead copper): 77.597,185.674 159.766,185.674 159.766,76.2 77.597,76.2

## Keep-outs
Board Outline Layer:
  lines w0.254: 84.455,86.229 148.455,86.229 148.455,181.229 84.455,181.229 84.455,86.229

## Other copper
Top Layer:
  region net GND: 92.073,127.396 92.581,127.396 92.581,126.995 92.067,126.995 92.073,127
  region net GND: 93.983,96.848 94.491,96.848 94.491,96.446 93.977,96.446 93.983,96.452
  region net GND: 96.015,92.403 96.523,92.403 96.523,92.001 96.009,92.001 96.015,92.007
  region net +1V8: 123.143,105.828 123.651,105.828 123.651,105.426 123.138,105.426 123.143,105.431
  region net GND: 121.662,103.797 122.17,103.797 122.17,103.396 121.657,103.396 121.662,103.401
  region: 93.094,127.074 93.602,127.074 93.602,126.672 93.088,126.672 93.094,126.678
  region: 93.983,126.693 94.491,126.693 94.491,126.291 93.977,126.291 93.983,126.297
Bottom Layer:
  region net DONE: 110.366,137.361 110.874,137.361 110.874,136.959 110.36,136.959 110.366,136.965
  region net PROGRAMN: 108.588,136.577 109.096,136.577 109.096,136.176 108.582,136.176 108.588,136.181
  region net INITN: 101.984,127.455 102.492,127.455 102.492,127.053 101.978,127.053 101.984,127.059
  region: 109.791,148.257 110.231,148.511 110.432,148.164 109.987,147.907 109.989,147.914

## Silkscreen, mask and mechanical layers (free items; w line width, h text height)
Top Silkscreen Layer:
  text "JTAG" at 144.674,166.326 h3.05 r90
